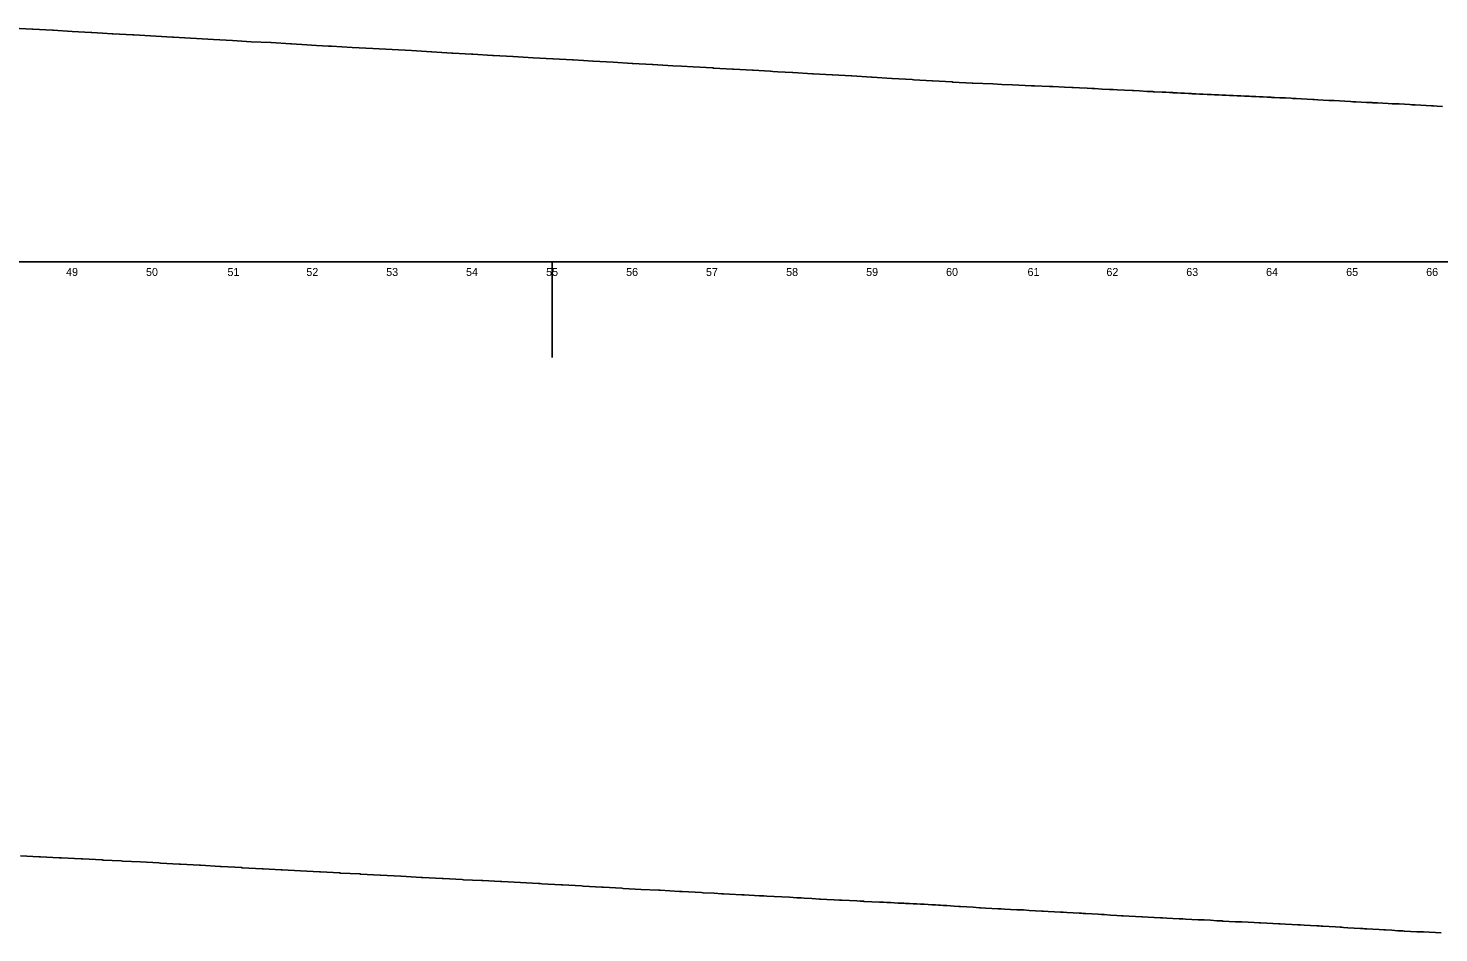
# Model space of a CAD drawing. Extents: x 579185 to 595036, y -53221 to -44640.
# Drawn here: x 583133 to 584896, y -45839 to -44708 of the extents above; entities that cross this region are included whole.
import ezdxf

# ---------------------------------------------------------------- set-up
doc = ezdxf.new("R2010")
doc.units = 0
for name, color, linetype in [('Default', 7, 'Continuous'), ('Exist Profile Cell', 7, 'Continuous'), ('Exist Vertical Profile Ground Line', 7, 'Continuous'), ('Exist Vertical Profile Horizontal Axis Label Major', 7, 'Continuous')]:
    doc.layers.add(name, color=color, linetype=linetype)

msp = doc.modelspace()

# ---------------------------------------------------------------- linework, layer by layer
at = {"layer": 'Default'}
msp.add_line((583787.9, -45119.4), (583787.9, -45000), dxfattribs=at)
at = {"layer": 'Exist Profile Cell'}
msp.add_line((579221, -45000), (594884.8, -45000), dxfattribs=at)
at = {"layer": 'Exist Vertical Profile Ground Line'}
for points in [[(583113.8, -44707.8), (583138.6, -44709), (583139, -44709.1), (583163.5, -44710.3), (583164.1, -44710.4), (583187.9, -44711.8), (583211.9, -44713.2), (583212.4, -44713.3), (583226, -44714), (583238.1, -44714.6), (583238.6, -44714.6), (583263.9, -44715.9), (583265.1, -44716), (583313.4, -44718.9), (583314.1, -44718.9), (583314.8, -44718.9), (583364.5, -44721.9), (583388.2, -44723.2), (583411.8, -44724.6), (583436.2, -44725.7), (583436.9, -44725.7), (583461.4, -44727.2), (583462, -44727.2), (583468.4, -44727.8), (583475.1, -44728.3), (583493.5, -44729.4), (583508.3, -44730.2), (583512, -44730.4)], [(583512, -44730.4), (583537.9, -44731.8), (583563.8, -44733.2), (583588, -44734.4), (583612.2, -44735.7), (583637.3, -44737.2), (583637.7, -44737.2), (583662.4, -44738.8), (583663.1, -44738.8), (583663.9, -44738.9), (583687.2, -44740.2), (583688.6, -44740.3), (583713.2, -44741.7), (583714, -44741.7), (583714.8, -44741.8), (583738.9, -44743.2), (583739.3, -44743.2), (583764, -44744.6), (583788.7, -44746), (583789, -44746), (583813.5, -44747.4), (583814, -44747.4), (583827.1, -44748.2), (583838.7, -44748.9), (583839.3, -44748.9), (583864, -44750.4), (583887.8, -44751.7), (583888.9, -44751.8), (583913, -44753.2), (583913.7, -44753.2), (583938.8, -44754.6), (583949.5, -44755.3), (583964.1, -44756.1), (583988.6, -44757.5), (583989.5, -44757.6), (584013.4, -44759), (584014.7, -44759.1), (584038.5, -44760.4), (584039.2, -44760.4), (584060.3, -44761.6), (584063.8, -44761.8), (584070, -44762.1), (584088.5, -44763.1), (584088.9, -44763.2), (584113.4, -44764.6), (584114.1, -44764.6), (584137.7, -44766), (584138.3, -44766), (584162.1, -44767.5), (584162.6, -44767.5), (584187.2, -44769), (584187.8, -44769), (584212.4, -44770.5), (584213, -44770.5), (584238, -44772), (584240.1, -44772.1), (584262.9, -44773.5), (584263.5, -44773.6), (584287.9, -44775), (584288.6, -44775.1), (584313.1, -44776.4), (584313.6, -44776.4), (584338.6, -44777.5), (584349.8, -44778), (584363.5, -44778.6), (584387, -44779.6), (584387.8, -44779.6), (584388.7, -44779.7), (584390.9, -44779.8), (584409.6, -44780.6), (584412.2, -44780.7), (584413.7, -44780.8), (584428.4, -44781.5), (584437.3, -44781.9), (584437.8, -44781.9), (584439, -44782), (584447.1, -44782.4), (584456.5, -44782.9), (584462.3, -44783.2), (584464.1, -44783.2), (584465.9, -44783.3), (584475.3, -44783.8), (584484.6, -44784.3), (584488, -44784.5), (584489.3, -44784.5), (584494, -44784.7), (584503.4, -44785.2), (584512.8, -44785.7), (584513.6, -44785.8), (584514.5, -44785.8), (584522.1, -44786.2), (584531.5, -44786.7), (584538.5, -44787), (584539.6, -44787.1), (584540.9, -44787.1), (584550.3, -44787.6), (584554.9, -44787.9), (584559.6, -44788.1), (584563.5, -44788.3), (584564.3, -44788.4), (584569, -44788.6)], [(584569, -44788.6), (584573.7, -44788.9), (584578.4, -44789.1), (584583.1, -44789.3), (584586.8, -44789.5), (584587.8, -44789.6), (584592.4, -44789.8), (584597.1, -44790.1), (584601.8, -44790.3), (584606.5, -44790.5), (584611.3, -44790.8), (584611.9, -44790.8), (584615.9, -44791), (584620.6, -44791.2), (584625.3, -44791.4), (584629.9, -44791.6), (584634.6, -44791.8), (584635.3, -44791.9), (584636.9, -44791.9), (584639.3, -44792), (584644, -44792.2), (584648.7, -44792.4), (584653.4, -44792.6), (584658.1, -44792.9), (584659.3, -44792.9), (584661.9, -44793), (584662.8, -44793.1), (584664.4, -44793.1), (584667.4, -44793.3), (584672.1, -44793.5), (584676.8, -44793.7), (584681.5, -44793.9), (584686.2, -44794.1), (584687.6, -44794.2), (584690.1, -44794.3), (584690.9, -44794.4), (584697.6, -44794.7), (584704.4, -44795), (584711.2, -44795.4), (584713.4, -44795.5), (584715.7, -44795.6), (584717.9, -44795.7), (584724.7, -44796.1), (584731.5, -44796.5), (584738.5, -44796.9), (584740.4, -44797), (584745, -44797.2), (584751.8, -44797.6), (584758.5, -44798), (584763.5, -44798.2), (584765.3, -44798.3), (584772.1, -44798.7), (584778.8, -44799), (584785.6, -44799.4), (584788.5, -44799.6), (584790, -44799.6), (584792.4, -44799.8), (584799.1, -44800.1), (584805.9, -44800.5), (584812.7, -44800.8), (584813.4, -44800.9), (584815.1, -44801), (584819.4, -44801.2), (584826.2, -44801.5), (584833, -44801.8), (584837.9, -44802.1), (584839.7, -44802.2), (584846.5, -44802.5), (584853.3, -44802.9), (584860, -44803.2), (584862.3, -44803.4), (584864.2, -44803.5), (584866.8, -44803.6), (584873.6, -44804), (584880.3, -44804.4), (584887.1, -44804.9), (584888, -44804.9), (584889.7, -44805), (584893.9, -44805.3), (584900.6, -44805.7)], [(583123.5, -45742.5), (583146.7, -45743.5), (583148.4, -45743.6), (583171.8, -45744.7), (583173.3, -45744.8), (583174.8, -45744.9), (583199.3, -45746.2), (583200.7, -45746.3), (583225.3, -45747.6), (583226.8, -45747.7), (583249.2, -45748.8), (583250.9, -45748.9), (583273.2, -45750), (583296.3, -45751.3), (583298.2, -45751.4), (583321.6, -45752.7), (583323.2, -45752.8), (583347.3, -45754.2), (583348.3, -45754.2), (583372.9, -45755.6), (583373.5, -45755.7), (583374.1, -45755.7), (583399.5, -45757.1), (583400.4, -45757.2), (583425.4, -45758.6), (583426.7, -45758.7), (583449.3, -45759.9), (583450.6, -45759.9), (583473.2, -45761.2), (583497.1, -45762.5), (583498.3, -45762.5), (583522.3, -45763.8), (583523.4, -45763.9), (583547.5, -45765.1), (583548.3, -45765.2), (583572.8, -45766.4), (583573.2, -45766.4), (583598.8, -45767.9), (583599.2, -45767.9), (583624.4, -45769.4), (583625.2, -45769.5), (583625.9, -45769.5), (583650.3, -45770.8), (583651.6, -45770.9), (583675.4, -45772.1), (583677.2, -45772.2), (583699.4, -45773.2), (583701.2, -45773.3), (583723.4, -45774.4), (583725.1, -45774.5), (583748.2, -45775.7), (583771, -45777), (583773.1, -45777.1), (583775.2, -45777.2), (583799, -45778.6), (583801, -45778.7), (583824.8, -45780.1), (583826.7, -45780.2), (583849.9, -45781.5), (583851.7, -45781.6), (583875, -45783), (583876.7, -45783.1)], [(583876.7, -45783.1), (583899, -45784.3), (583921.3, -45785.4), (583923, -45785.5), (583947, -45786.9), (583948.7, -45787), (583950.5, -45787.1), (583974.5, -45788.4), (583976.5, -45788.5), (583990.6, -45789.2), (583999.8, -45789.7), (584001.9, -45789.8), (584009.4, -45790.2), (584025.1, -45791), (584027.3, -45791.1), (584028.1, -45791.2), (584046.9, -45792.2), (584050, -45792.3), (584052.5, -45792.5), (584056.2, -45792.7), (584065.6, -45793.2), (584075, -45793.7), (584084.4, -45794.2), (584093.7, -45794.8), (584096.8, -45794.9), (584099.1, -45795.1), (584103.1, -45795.3), (584112.5, -45795.8), (584121.9, -45796.4), (584123.2, -45796.4), (584131.2, -45796.9), (584140.6, -45797.4), (584147.2, -45797.7), (584149.1, -45797.8), (584150, -45797.9), (584159.4, -45798.3), (584168.7, -45798.8), (584172.7, -45799), (584175, -45799.1), (584177.2, -45799.2), (584178.1, -45799.3), (584187.5, -45799.7), (584196.9, -45800.2), (584200, -45800.4), (584201.6, -45800.4), (584202.1, -45800.5), (584206.2, -45800.7), (584210.9, -45800.9), (584215.6, -45801.1), (584220.3, -45801.4), (584225, -45801.6), (584227.3, -45801.7), (584229.7, -45801.8), (584234.4, -45802.1), (584239.1, -45802.3), (584243.7, -45802.6), (584248.4, -45802.8), (584249.1, -45802.8), (584253.1, -45803), (584257.8, -45803.3), (584262.5, -45803.5), (584267.2, -45803.8), (584270.9, -45804), (584271.9, -45804.1), (584273.3, -45804.1), (584276.6, -45804.4), (584281.2, -45804.6), (584285.9, -45804.9), (584290.6, -45805.2), (584296.4, -45805.6), (584298.4, -45805.7), (584306.2, -45806.2), (584314, -45806.7), (584321.9, -45807.2), (584323.2, -45807.3), (584329.7, -45807.7), (584337.5, -45808.1), (584345.3, -45808.5), (584347.2, -45808.6), (584349, -45808.7), (584353.1, -45808.9), (584360.9, -45809.3), (584368.7, -45809.7), (584372.5, -45809.9), (584374.8, -45810), (584376.5, -45810.1), (584377, -45810.1), (584384.3, -45810.6), (584392.1, -45811), (584400, -45811.4), (584401.6, -45811.5), (584407.8, -45811.9), (584415.6, -45812.3), (584423.4, -45812.8), (584424.7, -45812.8), (584426.5, -45812.9), (584431.2, -45813.2), (584439, -45813.6), (584446.8, -45814.1), (584449.7, -45814.2), (584451.6, -45814.4)], [(584451.6, -45814.4), (584454.6, -45814.5), (584462.4, -45815), (584470.2, -45815.4), (584474.6, -45815.7), (584476.7, -45815.8), (584478, -45815.9), (584485.9, -45816.4), (584493.7, -45816.8), (584499.7, -45817.2), (584501.5, -45817.3), (584509.3, -45817.7), (584517.1, -45818.2), (584524.9, -45818.7), (584525.9, -45818.7), (584532.7, -45819), (584540.5, -45819.4), (584548.3, -45819.8), (584549.8, -45819.9), (584551, -45820), (584556.1, -45820.2), (584563.9, -45820.6), (584571.8, -45821), (584574.8, -45821.2), (584576.2, -45821.2), (584579.6, -45821.4), (584587.4, -45821.8), (584595.2, -45822.2), (584600.1, -45822.5), (584601.5, -45822.6), (584603, -45822.6), (584610.8, -45823), (584618.6, -45823.5), (584625.5, -45823.8), (584626.4, -45823.9), (584626.8, -45823.9), (584634.2, -45824.3), (584642, -45824.7), (584649.2, -45825), (584649.9, -45825.1), (584657.7, -45825.5), (584665.5, -45825.9), (584671.6, -45826.2), (584672.8, -45826.2), (584673.3, -45826.3), (584681.1, -45826.7), (584688.9, -45827.1), (584696.3, -45827.5), (584696.7, -45827.5), (584697.9, -45827.5), (584704.5, -45827.9), (584712.3, -45828.3), (584720.1, -45828.7), (584720.8, -45828.7), (584722.9, -45828.8), (584727.9, -45829.1), (584735.8, -45829.5), (584743.6, -45830), (584746.8, -45830.1), (584749, -45830.2), (584751.4, -45830.4), (584759.2, -45830.8), (584767, -45831.3), (584772.9, -45831.6), (584775, -45831.7), (584777.1, -45831.8), (584782.6, -45832.2), (584790.4, -45832.7), (584798.2, -45833.1), (584801.3, -45833.3), (584803.4, -45833.5), (584806, -45833.6), (584813.8, -45834.1), (584821.7, -45834.6), (584827.6, -45835), (584829.6, -45835.1), (584837.3, -45835.5), (584845.1, -45836), (584851.1, -45836.3), (584852.9, -45836.4), (584853.2, -45836.4), (584860.7, -45836.8), (584868.5, -45837.2), (584874.6, -45837.5), (584876.3, -45837.6), (584877.1, -45837.6), (584884.1, -45837.9), (584891.9, -45838.3), (584899, -45838.6)]]:
    msp.add_lwpolyline(points, dxfattribs=at)

# ---------------------------------------------------------------- texts
at = {"layer": 'Exist Vertical Profile Horizontal Axis Label Major'}
for s, p in [('49', (583180.4, -45017.5)), ('50', (583280.3, -45017.5)), ('51', (583382.1, -45017.5)), ('52', (583480.7, -45017.5)), ('53', (583580.5, -45017.5)), ('54', (583680.3, -45017.5)), ('55', (583780.4, -45017.5)), ('56', (583880.4, -45017.5)), ('57', (583980.2, -45017.5)), ('58', (584080.4, -45017.5)), ('59', (584180.4, -45017.5)), ('60', (584280.3, -45017.5)), ('61', (584382.1, -45017.5)), ('62', (584480.7, -45017.5)), ('63', (584580.5, -45017.5)), ('64', (584680.3, -45017.5)), ('65', (584780.4, -45017.5)), ('66', (584880.4, -45017.5))]:
    msp.add_text(s, height=10, dxfattribs=at).set_placement(p)

doc.saveas('drawing.dxf')
